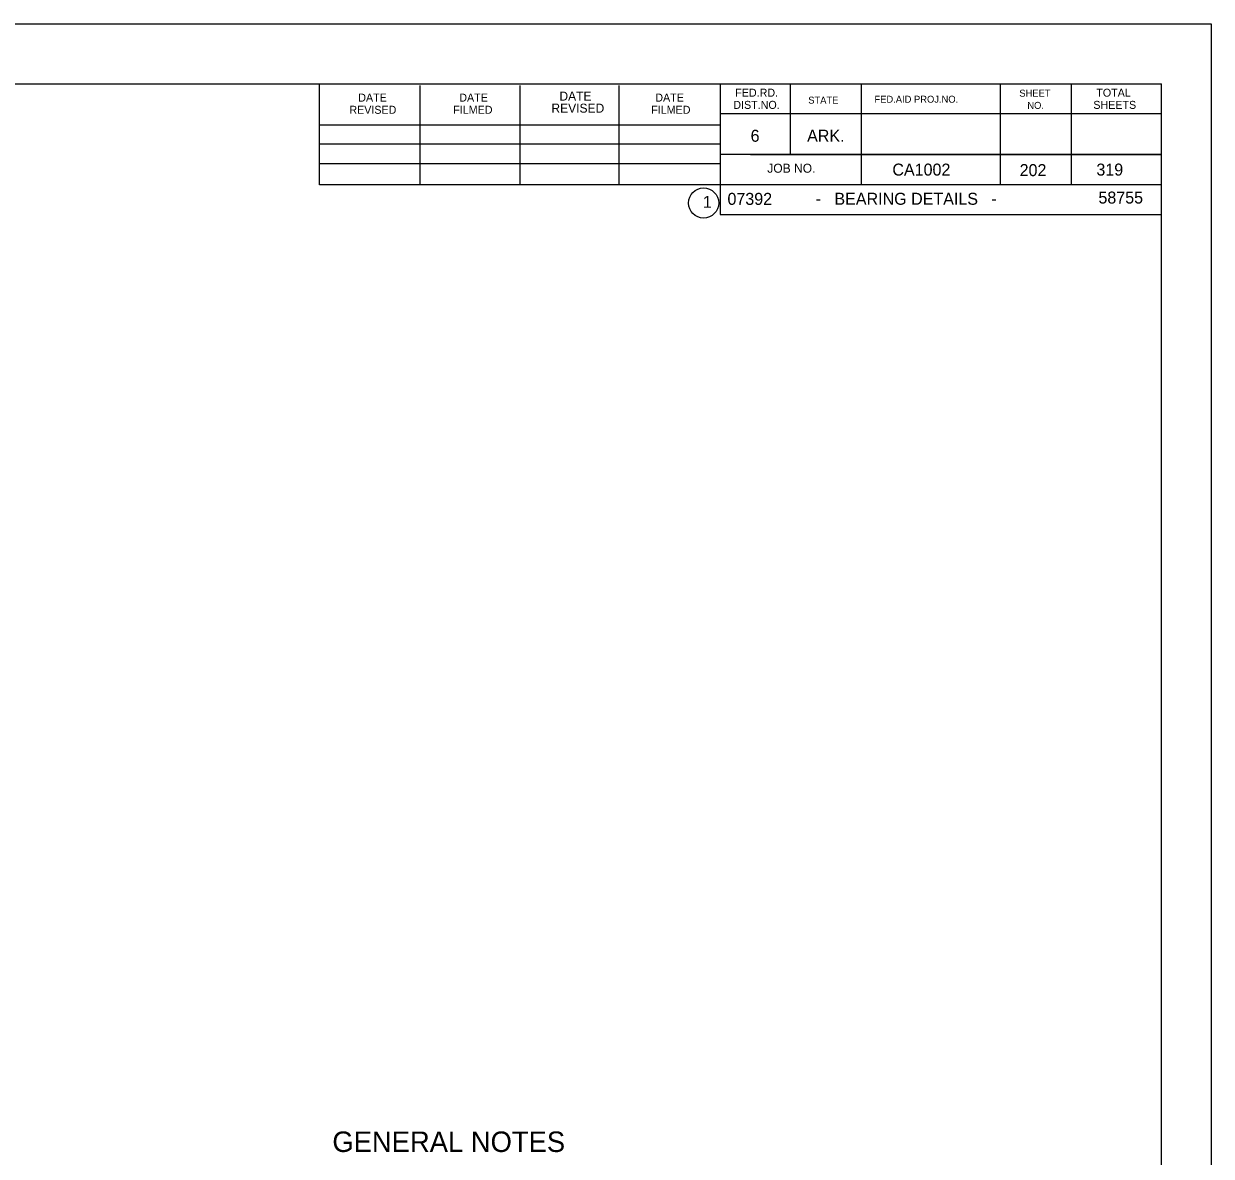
# Model space of a CAD drawing. Extents: x -193 to 149, y 507 to 725.
# Drawn here: x 32.6 to 148.7, y 614.5 to 725.2 of the extents above; entities that cross this region are included whole.
import ezdxf

# ---------------------------------------------------------------- set-up
doc = ezdxf.new("R2010")
doc.units = 0
for name, color, linetype in [('border', 7, 'Continuous'), ('Border 2660-Hwy18 - Level 62', 7, 'Continuous'), ('Border 2660-Hwy18 - Text', 7, 'Continuous'), ('Bridge No BLFR', 7, 'Continuous'), ('Level 41', 7, 'Continuous'), ('Text', 7, 'Continuous'), ('Title Text', 7, 'Continuous')]:
    doc.layers.add(name, color=color, linetype=linetype)

msp = doc.modelspace()

# ---------------------------------------------------------------- linework, layer by layer
at = {"layer": 'border'}
for p, q in [((-176.33, 719.31), (143.78, 719.31)), ((61.52, 709.44), (61.52, 719.31)), ((100.68, 719.31), (100.68, 706.52)), ((107.52, 719.31), (107.52, 712.38)), ((114.46, 719.31), (114.46, 709.44)), ((128.04, 719.31), (128.04, 709.44)), ((134.98, 719.31), (134.98, 709.44)), ((143.78, 513.86), (143.78, 719.31)), ((71.37, 709.44), (71.37, 719.12)), ((81.14, 709.44), (81.14, 719.12)), ((90.81, 709.44), (90.81, 719.12)), ((143.78, 716.37), (100.68, 716.37)), ((143.78, 716.4), (143.78, 716.4)), ((61.52, 715.29), (100.68, 715.29)), ((61.52, 713.43), (100.68, 713.43)), ((143.78, 712.38), (100.68, 712.38)), ((103.64, 712.38), (143.78, 712.38)), ((61.52, 709.44), (61.52, 711.5)), ((61.52, 711.5), (100.68, 711.5)), ((143.78, 709.44), (61.52, 709.44)), ((100.68, 706.52), (143.78, 706.52))]:
    msp.add_line(p, q, dxfattribs=at)
msp.add_circle((99.06, 707.65), 1.47, dxfattribs=at)
at = {"layer": 'Border 2660-Hwy18 - Level 62'}
msp.add_lwpolyline([(-192.53, 725.17), (148.65, 725.17), (148.65, 507.07), (-192.53, 507.07)], close=True, dxfattribs=at)

# ---------------------------------------------------------------- texts
at = {"layer": 'Border 2660-Hwy18 - Text'}
for s, height, p in [('DATE', 0.782, (65.32, 717.56)), ('DATE', 0.782, (75.19, 717.56)), ('DATE', 0.879, (84.97, 717.66)), ('DATE', 0.782, (94.34, 717.56)), ('FED.RD.', 0.782, (102.15, 718.04)), ('FED.AID PROJ.NO.', 0.6839, (115.75, 717.45)), ('SHEET', 0.684, (129.9, 718.04)), ('TOTAL', 0.782, (137.42, 718.04)), ('REVISED', 0.782, (64.45, 716.37)), ('FILMED', 0.782, (74.6, 716.37)), ('REVISED', 0.879, (84.19, 716.48)), ('FILMED', 0.782, (93.94, 716.37)), ('DIST.NO.', 0.782, (101.96, 716.85)), ('STATE', 0.684, (109.28, 717.36)), ('NO.', 0.684, (130.68, 716.85)), ('SHEETS', 0.782, (137.13, 716.85)), ('6', 1.17, (103.65, 713.64)), ('ARK.', 1.172, (109.17, 713.64)), ('JOB NO.', 0.879, (105.28, 710.61)), ('CA1002', 1.172, (117.5, 710.33)), ('319', 1.172, (137.43, 710.33)), ('1', 1.17, (98.99, 707.18))]:
    msp.add_text(s, height=height, dxfattribs=at).set_placement(p)
at = {"layer": 'Bridge No BLFR'}
msp.add_text('07392', height=1.172, dxfattribs=at).set_placement((101.39, 707.47))
at = {"layer": 'Level 41'}
msp.add_text('GENERAL NOTES', height=2, dxfattribs=at).set_placement((62.79, 614.92))
at = {"layer": 'Text'}
msp.add_text('202', height=1.172, dxfattribs=at).set_placement((129.93, 710.28))
at = {"layer": 'Title Text'}
for s, height, p in [('-   BEARING DETAILS   -', 1.1722, (110.01, 707.48)), ('58755', 1.172, (137.63, 707.6))]:
    msp.add_text(s, height=height, dxfattribs=at).set_placement(p)

doc.saveas('drawing.dxf')
